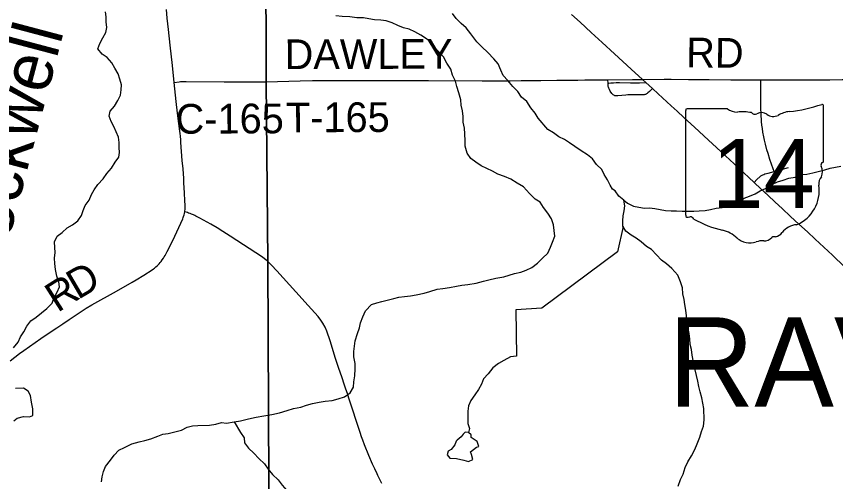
# Model space of a CAD drawing. Extents: x 0 to 34, y 0 to 22.
# Drawn here: x 4.562 to 6.128, y 15.681 to 16.57 of the extents above; entities that cross this region are included whole.
import ezdxf

# ---------------------------------------------------------------- set-up
doc = ezdxf.new("R2010")
doc.units = 0
for name, color, linetype in [('GM_X_Corporation', 7, 'Continuous'), ('GM_X_County_Road', 7, 'Continuous'), ('GM_X_County_Road_Text', 7, 'Continuous'), ('GM_X_Major_Lake', 7, 'Continuous'), ('GM_X_Major_Lake_Text', 7, 'Continuous'), ('GM_X_Minor_Lake', 7, 'Continuous'), ('GM_X_Minor_River', 7, 'Continuous'), ('GM_X_State_Route', 7, 'Continuous'), ('GM_X_State_Shield', 7, 'Continuous'), ('GM_X_Township_Road', 7, 'Continuous'), ('GM_X_Township_Road_Text', 7, 'Continuous'), ('GM_X_Township_Text', 7, 'Continuous')]:
    doc.layers.add(name, color=color, linetype=linetype)

msp = doc.modelspace()

# ---------------------------------------------------------------- linework, layer by layer
at = {"layer": 'GM_X_Corporation'}
for points in [[(2.114, 13.8173), (5.0539, 13.8173), (5.0552, 14.1423), (5.0521, 14.2095), (5.0518, 14.2807), (5.0535, 14.3223), (5.0506, 14.4841), (5.0493, 14.6873), (5.0428, 16.1022), (5.0398, 16.4459), (5.0375, 17.2161), (5.0375, 17.2177), (5.0364, 17.2177), (4.9837, 17.2182), (4.8829, 17.219), (4.8603, 17.2191), (4.8453, 17.219), (4.8174, 17.2186), (4.7998, 17.2177), (4.7904, 17.2169), (4.7848, 17.216), (4.7806, 17.215), (4.732, 17.2135), (3.7259, 17.2107)], [(5.0375, 17.2161), (5.0398, 16.4459), (5.0428, 16.1022), (5.0493, 14.6873)]]:
    msp.add_lwpolyline(points, dxfattribs=at)
at = {"layer": 'GM_X_County_Road'}
for points in [[(4.8639, 16.4439), (4.8606, 16.4761), (4.8564, 16.5149), (4.8531, 16.5452), (4.8505, 16.5668), (4.849, 16.5835)], [(4.8639, 16.4439), (4.8731, 16.4452), (4.8757, 16.4456), (4.8784, 16.4458), (4.8811, 16.4459), (4.8871, 16.446), (4.9596, 16.4452), (5.04, 16.4453)], [(4.8841, 16.1965), (4.8845, 16.1989), (4.8848, 16.2012), (4.8848, 16.2037), (4.8849, 16.2063), (4.8849, 16.2092), (4.8843, 16.2178), (4.8837, 16.2328), (4.8825, 16.2519), (4.8821, 16.2606), (4.8808, 16.2791), (4.8793, 16.2946), (4.8768, 16.3293), (4.8765, 16.3345), (4.876, 16.3416), (4.8755, 16.3465), (4.875, 16.3509), (4.8703, 16.3853), (4.8677, 16.4075), (4.8639, 16.4439)], [(4.5504, 15.9118), (4.5685, 15.9261), (4.5765, 15.932), (4.6089, 15.9549), (4.6211, 15.9633), (4.6396, 15.9753), (4.6509, 15.9825), (4.6633, 15.9909), (4.6859, 16.0064), (4.6954, 16.0125), (4.7062, 16.0188), (4.7538, 16.0455), (4.7834, 16.0625), (4.791, 16.0669), (4.806, 16.0757), (4.8221, 16.0861), (4.8246, 16.088), (4.8265, 16.0894), (4.8291, 16.0916), (4.8312, 16.0934), (4.8331, 16.0953), (4.8351, 16.0974), (4.8371, 16.0998), (4.839, 16.1021), (4.8411, 16.105), (4.8433, 16.1081), (4.845, 16.1108), (4.8466, 16.1133), (4.8485, 16.1169), (4.8507, 16.1209), (4.8611, 16.1421), (4.8729, 16.1668), (4.8804, 16.1835), (4.8813, 16.1862), (4.882, 16.1881), (4.8828, 16.1908), (4.8834, 16.1934), (4.8841, 16.1965)], [(5.043, 16.1016), (5.0413, 16.1031), (5.0363, 16.1072), (5.0324, 16.11), (4.971, 16.1502), (4.957, 16.1594), (4.9459, 16.1663), (4.9341, 16.1732), (4.9132, 16.1847), (4.9094, 16.1868), (4.9055, 16.1887), (4.9032, 16.1898), (4.9006, 16.191), (4.8968, 16.1926), (4.8945, 16.1935), (4.8914, 16.1945), (4.8892, 16.1952), (4.8868, 16.1958), (4.8841, 16.1965)], [(5.261, 15.6776), (5.2575, 15.6842), (5.2533, 15.6927), (5.2517, 15.696), (5.2472, 15.7055), (5.2431, 15.7146), (5.2361, 15.7311), (5.2279, 15.7513), (5.2244, 15.7605), (5.222, 15.7671), (5.2193, 15.7749), (5.1976, 15.841), (5.1949, 15.8495), (5.192, 15.8582), (5.189, 15.8677), (5.185, 15.8796), (5.1782, 15.8991), (5.1724, 15.9167), (5.1617, 15.9502), (5.1555, 15.9686), (5.1523, 15.9761), (5.1482, 15.9838), (5.1444, 15.9896), (5.1391, 15.9966), (5.1263, 16.011), (5.1201, 16.0181), (5.0966, 16.0437), (5.0601, 16.0843), (5.0501, 16.0949), (5.0449, 16.1), (5.044, 16.1008), (5.043, 16.1016)]]:
    msp.add_lwpolyline(points, dxfattribs=at)
at = {"layer": 'GM_X_Major_Lake'}
msp.add_lwpolyline([(4.5569, 15.9372), (4.5655, 15.9475), (4.5703, 15.9578), (4.5767, 15.9674), (4.5823, 15.9784), (4.5902, 15.9887), (4.6, 15.9956), (4.6101, 16.0036), (4.6203, 16.0121), (4.6304, 16.022), (4.6337, 16.0315), (4.6401, 16.0433), (4.6445, 16.0532), (4.6433, 16.063), (4.6395, 16.074), (4.6371, 16.0865), (4.6355, 16.0982), (4.6354, 16.1081), (4.6364, 16.1191), (4.636, 16.1286), (4.6352, 16.1396), (4.64, 16.1502), (4.6498, 16.1571), (4.6595, 16.1659), (4.6693, 16.1721), (4.6795, 16.1794), (4.6866, 16.1897), (4.6899, 16.1992), (4.6937, 16.2087), (4.7015, 16.219), (4.706, 16.2296), (4.7108, 16.2391), (4.7179, 16.2487), (4.7284, 16.2601), (4.7352, 16.27), (4.7438, 16.28), (4.7513, 16.2914), (4.7584, 16.3009), (4.7595, 16.3104), (4.759, 16.3199), (4.7589, 16.3294), (4.7573, 16.3396), (4.7527, 16.3498), (4.7485, 16.3596), (4.7435, 16.3694), (4.7396, 16.3793), (4.7414, 16.3891), (4.7497, 16.3987), (4.756, 16.4097), (4.7613, 16.4196), (4.7627, 16.4299), (4.7634, 16.4394), (4.7603, 16.4503), (4.7568, 16.4602), (4.7506, 16.4711), (4.7449, 16.4813), (4.7357, 16.4915), (4.7262, 16.4982), (4.7178, 16.5084), (4.7219, 16.5183), (4.7275, 16.529), (4.7334, 16.5392), (4.7349, 16.5491), (4.734, 16.5597), (4.7336, 16.5692), (4.7327, 16.5791)], dxfattribs=at)
at = {"layer": 'GM_X_Minor_Lake'}
msp.add_line((5.4031, 15.7588), (5.4005, 15.7519), dxfattribs=at)
for points in [[(4.5576, 15.7977), (4.564, 15.8027), (4.5757, 15.8058), (4.5871, 15.8051), (4.5939, 15.8078), (4.5938, 15.8204), (4.591, 15.8328), (4.5894, 15.8461), (4.5848, 15.8544), (4.576, 15.86), (4.5605, 15.8592)], [(5.4005, 15.7519), (5.3934, 15.7428), (5.3873, 15.7393), (5.3855, 15.7328), (5.3905, 15.7264), (5.4037, 15.7254), (5.4177, 15.7225), (5.4265, 15.7199), (5.4344, 15.7237), (5.432, 15.7332), (5.4301, 15.7381), (5.4418, 15.7469), (5.4459, 15.7485), (5.4428, 15.7579), (5.4375, 15.7617), (5.4318, 15.7658), (5.4314, 15.7707), (5.4264, 15.7753), (5.4203, 15.7756), (5.4162, 15.7721), (5.4125, 15.7672), (5.4046, 15.7607), (5.4031, 15.7588)]]:
    msp.add_lwpolyline(points, dxfattribs=at)
at = {"layer": 'GM_X_Minor_River'}
for p, q in [((5.7221, 16.1686), (5.7109, 16.1202)), ((5.7109, 16.1202), (5.5668, 16.0129))]:
    msp.add_line(p, q, dxfattribs=at)
for points in [[(5.5699, 16.2048), (5.5633, 16.2154), (5.5538, 16.221), (5.5428, 16.2319), (5.5317, 16.2443), (5.5195, 16.2515), (5.507, 16.2589), (5.4952, 16.2642), (5.4827, 16.269), (5.472, 16.2746), (5.4614, 16.2798), (5.4508, 16.2847), (5.4405, 16.2914), (5.431, 16.2989), (5.4237, 16.3087), (5.4198, 16.3223), (5.4201, 16.3322), (5.4196, 16.3455), (5.4188, 16.3565), (5.416, 16.3678), (5.4163, 16.3788), (5.4151, 16.3898), (5.4124, 16.4004), (5.4119, 16.411), (5.4076, 16.4239), (5.4038, 16.4364), (5.4018, 16.4466), (5.3956, 16.4579), (5.3929, 16.4696), (5.3852, 16.481), (5.3787, 16.4927), (5.3635, 16.5088), (5.3554, 16.5194), (5.3459, 16.5273), (5.3356, 16.534), (5.3238, 16.5404), (5.3132, 16.5456), (5.3022, 16.5486), (5.2916, 16.5527), (5.2806, 16.5579), (5.2688, 16.5616), (5.2589, 16.563), (5.2468, 16.5637), (5.2362, 16.5655), (5.226, 16.5673), (5.2131, 16.5672), (5.1995, 16.5694), (5.1851, 16.57), (5.1726, 16.5715)], [(5.7019, 16.2402), (5.6971, 16.2475), (5.6921, 16.2581), (5.6859, 16.2679), (5.6813, 16.2777), (5.671, 16.2875), (5.6634, 16.2977), (5.6538, 16.3056), (5.6417, 16.3131), (5.6299, 16.3213), (5.6196, 16.3284), (5.6097, 16.3348), (5.5991, 16.34), (5.5888, 16.3479), (5.5781, 16.3543), (5.5598, 16.3754), (5.5537, 16.3852), (5.5453, 16.3954), (5.538, 16.4078), (5.5277, 16.4161), (5.5208, 16.4266), (5.5113, 16.436), (5.5017, 16.4477), (5.4929, 16.4575), (5.4883, 16.4677), (5.4833, 16.4794), (5.4749, 16.4892), (5.4634, 16.5009), (5.452, 16.5122), (5.4421, 16.5216), (5.431, 16.537), (5.4222, 16.548), (5.4123, 16.5566), (5.4027, 16.566), (5.3955, 16.5758)], [(5.723, 16.2193), (5.7303, 16.2136), (5.7417, 16.2073), (5.7519, 16.2055), (5.7625, 16.204), (5.7723, 16.2041), (5.7826, 16.203), (5.7928, 16.2009), (5.8027, 16.1994), (5.814, 16.1984), (5.8239, 16.1984), (5.8348, 16.1981), (5.8462, 16.1982), (5.8568, 16.1979), (5.867, 16.1984), (5.8784, 16.1992), (5.8886, 16.2012), (5.8999, 16.2036), (5.9109, 16.2052), (5.9218, 16.2094), (5.9324, 16.2133), (5.9426, 16.2168), (5.9535, 16.2229), (5.9637, 16.2268), (5.9742, 16.2311), (5.984, 16.2368), (5.9942, 16.2411), (6.0059, 16.2487), (6.0172, 16.2541), (6.0278, 16.2573), (6.0387, 16.2608), (6.0508, 16.2631), (6.0621, 16.2681), (6.0727, 16.269), (6.0844, 16.2713), (6.0969, 16.2745), (6.1071, 16.2772), (6.1177, 16.2803), (6.1279, 16.2819), (6.1377, 16.2843)], [(5.805, 16.0974), (5.7951, 16.1042), (5.7855, 16.1147), (5.776, 16.1249), (5.7665, 16.1305), (5.7562, 16.1395), (5.7467, 16.1463), (5.7372, 16.1523), (5.7273, 16.1598), (5.7215, 16.1696), (5.7214, 16.1794), (5.7221, 16.1893), (5.7239, 16.1988), (5.725, 16.2083), (5.723, 16.2193), (5.7135, 16.2268), (5.707, 16.237), (5.7019, 16.2402)], [(4.7247, 15.6811), (4.7265, 15.6906), (4.7287, 15.7004), (4.7324, 15.7103), (4.7425, 15.7222), (4.7493, 15.7317), (4.7583, 15.7412), (4.7692, 15.7466), (4.7828, 15.7532), (4.7971, 15.7571), (4.8081, 15.7598), (4.819, 15.763), (4.8326, 15.7684), (4.8424, 15.7719), (4.8523, 15.7735), (4.8651, 15.7762), (4.8776, 15.7797), (4.8889, 15.7851), (4.8991, 15.7882), (4.9093, 15.7887), (4.9316, 15.7892), (4.9433, 15.7912), (4.9543, 15.7943), (4.9641, 15.7929), (4.9785, 15.7957), (4.9906, 15.7977), (5.0057, 15.8012), (5.0208, 15.8043), (5.0352, 15.8071), (5.0503, 15.8095), (5.065, 15.813), (5.0801, 15.8169), (5.0922, 15.8208), (5.1058, 15.8236), (5.1168, 15.8271), (5.1285, 15.8306), (5.1413, 15.8333), (5.1523, 15.8353), (5.1659, 15.8366), (5.1772, 15.8393), (5.1897, 15.8436), (5.2002, 15.8509), (5.2066, 15.8615), (5.2073, 15.8721), (5.2091, 15.8832), (5.2097, 15.8968), (5.2096, 15.9067), (5.2073, 15.9195), (5.2072, 15.9298), (5.2082, 15.94), (5.21, 15.9503), (5.2145, 15.964), (5.2178, 15.975), (5.22, 15.9849), (5.2244, 15.9963), (5.2296, 16.0077), (5.2413, 16.0195), (5.2511, 16.0226), (5.2609, 16.0254), (5.2711, 16.0277), (5.2836, 16.0312), (5.2934, 16.0336), (5.304, 16.0352), (5.3157, 16.036), (5.3263, 16.038), (5.3414, 16.0415), (5.3527, 16.0447), (5.3667, 16.0489), (5.3773, 16.0505), (5.3901, 16.0525), (5.4034, 16.0549), (5.4136, 16.0565), (5.4253, 16.0581), (5.4408, 16.0605), (5.4548, 16.0644), (5.4653, 16.0671), (5.4786, 16.0699), (5.4937, 16.0723), (5.5043, 16.0758), (5.5145, 16.0789), (5.5265, 16.0816), (5.5367, 16.0851), (5.5473, 16.0901), (5.5582, 16.0986), (5.568, 16.1081), (5.5777, 16.1181), (5.5833, 16.1295), (5.587, 16.139), (5.5911, 16.1504), (5.5903, 16.161), (5.589, 16.1716), (5.5848, 16.1833), (5.5783, 16.1943), (5.5699, 16.2048)], [(5.8273, 15.6729), (5.8317, 15.6851), (5.8366, 15.6954), (5.8406, 15.7083), (5.8455, 15.719), (5.8526, 15.7308), (5.8589, 15.743), (5.8637, 15.7536), (5.8685, 15.7662), (5.8715, 15.7768), (5.8756, 15.7874), (5.877, 15.7996), (5.8761, 15.8208), (5.8741, 15.831), (5.8721, 15.8416), (5.8694, 15.853), (5.8666, 15.8632), (5.8647, 15.8731), (5.8623, 15.884), (5.8588, 15.8977), (5.8564, 15.9098), (5.8541, 15.9226), (5.8528, 15.9336), (5.8501, 15.9435), (5.8496, 15.9541), (5.8484, 15.9643), (5.8465, 15.9745), (5.8441, 15.9866), (5.8432, 15.998), (5.842, 16.009), (5.8397, 16.0196), (5.8388, 16.0294), (5.8361, 16.0404), (5.8352, 16.0518), (5.8314, 16.0631), (5.8267, 16.0756), (5.8149, 16.0884), (5.805, 16.0974)], [(5.5668, 16.0129), (5.5169, 16.0095), (5.518, 15.9212), (5.5066, 15.9196), (5.4942, 15.913), (5.4836, 15.9069), (5.4731, 15.8985), (5.4641, 15.8874), (5.4551, 15.8779), (5.4514, 15.8672), (5.4458, 15.8573), (5.4383, 15.8474), (5.4308, 15.836), (5.4264, 15.8264), (5.4253, 15.8158), (5.4254, 15.8041), (5.4251, 15.7923), (5.4282, 15.7825), (5.4264, 15.7753)], [(4.9785, 15.7957), (4.9908, 15.7753), (4.9977, 15.7651), (4.9985, 15.7552), (5.0061, 15.7454), (5.0164, 15.7357), (5.0256, 15.7255), (5.0363, 15.7153), (5.0435, 15.7048), (5.0516, 15.695), (5.0626, 15.6845), (5.0703, 15.6747), (5.0791, 15.6645), (5.0791, 15.6626)]]:
    msp.add_lwpolyline(points, dxfattribs=at)
at = {"layer": 'GM_X_State_Route'}
for points in [[(5.6235, 16.5736), (5.6396, 16.5589), (5.6611, 16.5392), (5.6817, 16.5203), (5.7056, 16.4985), (5.7372, 16.4695), (5.7589, 16.4497)], [(5.7589, 16.4497), (5.7654, 16.4438), (5.7781, 16.4321), (5.7886, 16.4225), (5.8137, 16.3993), (5.8251, 16.3889), (5.8379, 16.377), (5.8582, 16.3586), (5.885, 16.3336), (5.9001, 16.3198), (5.9175, 16.3038), (5.9422, 16.2806), (5.9722, 16.2529), (5.9853, 16.2407), (5.9983, 16.2284), (6.0125, 16.2152), (6.0258, 16.203), (6.0417, 16.1881), (6.0577, 16.1734), (6.074, 16.1584), (6.0892, 16.1443), (6.1056, 16.1293), (6.1223, 16.1138), (6.1453, 16.0916)]]:
    msp.add_lwpolyline(points, dxfattribs=at)
at = {"layer": 'GM_X_State_Shield'}
for p, q in [((5.9212, 16.3938), (5.844, 16.3938)), ((6.1051, 16.2941), (6.1051, 16.3987)), ((5.8414, 16.3903), (5.8414, 16.1902)), ((6.1051, 16.2941), (6.1051, 16.2941))]:
    msp.add_line(p, q, dxfattribs=at)
for centre, radius, start, end in [((5.8445, 16.3908), 0.00305, 98.1301, 188.1301), ((5.9396, 16.417), 0.0296, 231.6195, 271.1119), ((6.0112, 16.6666), 0.2796, 275.8445, 288.9065), ((6.1022, 16.3992), 0.00294, 351.8621, 97.738), ((5.9495, 16.2814), 0.1064, 80.4867, 94.9883), ((5.9736, 16.3918), 0.00855, 219.7921, 297.1024), ((5.9862, 16.3687), 0.0178, 54.4667, 119.1411), ((6.0091, 16.4004), 0.0214, 233.8562, 294.8282), ((6.0468, 16.3327), 0.0563, 97.3462, 120.7689), ((6.1044, 16.2864), 0.00454, 107.944, 210.337), ((6.0755, 16.2731), 0.0273, 340.033, 23.6496), ((6.102, 16.2936), 0.00314, 289.6038, 7.7341), ((6.1156, 16.2502), 0.0198, 136.8065, 186.9296), ((6.0268, 16.2369), 0.0699, 292.3089, 8.9858), ((5.8445, 16.1898), 0.00308, 171.9584, 258.3066), ((5.8449, 16.2102), 0.0235, 267.339, 280.6039), ((5.8498, 16.1787), 0.00848, 29.7484, 93.2717), ((5.9568, 16.3585), 0.2019, 240.4129, 257.1985), ((5.8966, 16.1003), 0.0632, 47.1842, 75.836), ((6.0563, 16.134), 0.0383, 94.4031, 142.5768), ((5.9649, 16.1777), 0.0401, 230.7004, 286.2918), ((5.991, 16.1627), 0.0214, 268.777, 315.5493), ((6.0104, 16.1433), 0.00601, 65.7517, 132.6484), ((6.0078, 16.1708), 0.0226, 282.8732, 323.2771), ((5.9881, 16.1085), 0.0329, 85.6951, 111.2099)]:
    msp.add_arc(centre, radius, start, end, dxfattribs=at)
at = {"layer": 'GM_X_Township_Road'}
msp.add_line((6.0106, 16.2738), (6.0382, 16.2812), dxfattribs=at)
for points in [[(5.04, 16.4453), (5.1048, 16.4472), (5.128, 16.4475), (5.1696, 16.4476), (5.1964, 16.4474), (5.2121, 16.4474), (5.2272, 16.4474), (5.2659, 16.4476), (5.3502, 16.4475), (5.4527, 16.4469), (5.4665, 16.4469), (5.4843, 16.447), (5.4933, 16.4471), (5.5042, 16.4473), (5.5062, 16.4473)], [(5.5062, 16.4473), (5.5272, 16.4475), (5.5647, 16.4479), (5.5952, 16.4483), (5.6095, 16.4484), (5.6224, 16.4485), (5.6352, 16.4486), (5.6487, 16.4487), (5.6721, 16.4489), (5.683, 16.4491), (5.6929, 16.4491)], [(5.6929, 16.4491), (5.7399, 16.4494), (5.7589, 16.4497)], [(5.7781, 16.4321), (5.7721, 16.4267), (5.7689, 16.4239), (5.7678, 16.423), (5.7668, 16.4223), (5.7657, 16.4217), (5.7646, 16.4212), (5.7634, 16.4209), (5.7621, 16.4206), (5.7607, 16.4204), (5.7572, 16.4202), (5.7536, 16.4201), (5.7436, 16.4201), (5.7349, 16.4201), (5.7309, 16.42), (5.7269, 16.4197), (5.7118, 16.4183), (5.7104, 16.4182), (5.7091, 16.4182), (5.7082, 16.4183), (5.7072, 16.4184), (5.7063, 16.4186), (5.7054, 16.4189), (5.7041, 16.4195), (5.703, 16.4204), (5.7022, 16.421), (5.7006, 16.4228), (5.6974, 16.4272), (5.6956, 16.4304), (5.6943, 16.4333), (5.6939, 16.4348), (5.6936, 16.4362), (5.6933, 16.4378), (5.6933, 16.4393), (5.6932, 16.4423), (5.6929, 16.4491)], [(5.6932, 16.4423), (5.6949, 16.4425), (5.6987, 16.443), (5.7035, 16.4434), (5.7084, 16.4436), (5.7147, 16.4437), (5.7358, 16.4435), (5.7534, 16.4435), (5.7654, 16.4438)], [(5.7589, 16.4497), (5.8005, 16.4502), (5.8135, 16.4502), (5.8468, 16.4499), (5.8862, 16.4494), (5.9276, 16.449), (5.985, 16.449)], [(5.985, 16.449), (6.0157, 16.449), (6.0822, 16.449), (6.0977, 16.4491), (6.1169, 16.4492), (6.1405, 16.4496), (6.175, 16.4499)], [(6.0106, 16.2738), (6.0089, 16.2788), (6.0025, 16.2969), (5.9989, 16.3081), (5.9968, 16.315), (5.9937, 16.3259), (5.9919, 16.3338), (5.9907, 16.3398), (5.9892, 16.3488), (5.9881, 16.3558), (5.9873, 16.3626), (5.9866, 16.3691), (5.9863, 16.3728), (5.9858, 16.3806), (5.9856, 16.385), (5.9855, 16.3873), (5.9854, 16.3909), (5.9853, 16.4057), (5.9851, 16.4453), (5.985, 16.449)], [(5.9722, 16.2529), (5.9777, 16.2586), (5.9838, 16.2641), (5.9853, 16.2653), (5.9874, 16.2667), (5.989, 16.2676), (5.9906, 16.2683), (5.9929, 16.2691), (5.9989, 16.2708), (6.0106, 16.2738)]]:
    msp.add_lwpolyline(points, dxfattribs=at)

# ---------------------------------------------------------------- texts
at = {"layer": 'GM_X_County_Road_Text'}
for s, height, rotation, p in [('C-165', 0.05682, 0.2768, (4.8666, 16.3459)), ('D', 0.0568, 30.434, (4.6799, 16.0281)), ('R', 0.0568, 32.5014, (4.641, 16.0033))]:
    msp.add_text(s, height=height, rotation=rotation, dxfattribs=at).set_placement(p)
at = {"layer": 'GM_X_Major_Lake_Text'}
msp.add_text('Rockwell', height=0.09473, rotation=75.1742, dxfattribs=at).set_placement((4.5237, 16.052))
at = {"layer": 'GM_X_State_Shield'}
msp.add_text('14', height=0.13184, dxfattribs=at).set_placement((5.892, 16.2043))
at = {"layer": 'GM_X_Township_Road_Text'}
for s, rotation, p in [('DAWLEY', 0.1553, (5.075, 16.4694)), ('RD', 359.5089, (5.8422, 16.4728)), ('T-165', 0.2739, (5.0775, 16.3485))]:
    msp.add_text(s, height=0.05682, rotation=rotation, dxfattribs=at).set_placement(p)
at = {"layer": 'GM_X_Township_Text'}
msp.add_text('RAVENNA', height=0.17045, rotation=0, dxfattribs=at).set_placement((5.8081, 15.8246))

doc.saveas('drawing.dxf')
